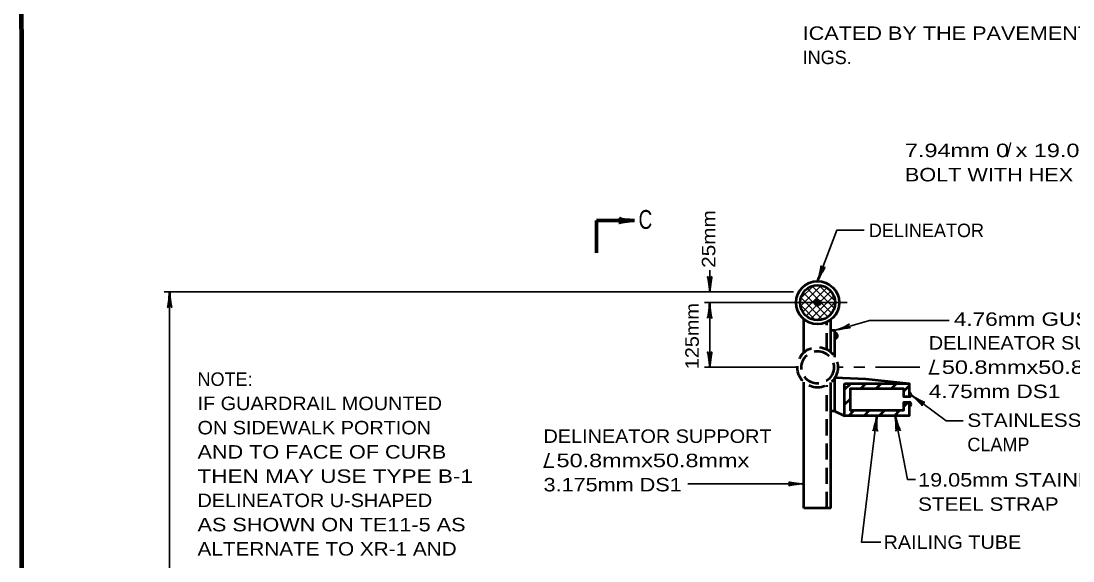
# Model space of a CAD drawing. Extents: x -105 to 751, y -65 to 479.
# Drawn here: x -47.6 to 186.6, y 91.1 to 211.4 of the extents above; entities that cross this region are included whole.
import ezdxf

# ---------------------------------------------------------------- set-up
doc = ezdxf.new("R2010")
doc.units = 0
doc.header["$LTSCALE"] = 1.2
doc.linetypes.add('MEDIUM_DASHED', pattern=[4.5, 3, -1.5])
doc.layers.add('1', color=7, linetype='Continuous', lineweight=35)

msp = doc.modelspace()

# ---------------------------------------------------------------- hatches: boundary and pattern name
at = {"layer": '1'}
msp.add_hatch(color=256, dxfattribs=at).paths.add_polyline_path([(130.319, 148.648, 1), (129.119, 148.648, 1)])

# ---------------------------------------------------------------- linework, layer by layer
at = {"layer": '1', "lineweight": 70}
for q in [(88.925, 166.96), (80.525, 159.76)]:
    msp.add_line((80.525, 166.96), q, dxfattribs=at)
at = {"layer": '1'}
for p, q in [((105.719, 151.048), (105.719, 155.848)), ((125.917, 147.83), (130.537, 152.45)), ((125.936, 149.546), (128.821, 152.431)), ((133.422, 147.424), (128.497, 152.35)), ((133.595, 148.948), (130.019, 152.525)), ((-15.697, 151.048), (124.362, 151.048)), ((-14.497, 13.539), (-14.497, 151.048)), ((126.403, 146.619), (131.748, 151.964)), ((131.98, 145.472), (126.544, 150.908)), ((127.183, 145.701), (132.666, 151.185)), ((132.838, 146.311), (127.383, 151.766)), ((128.233, 145.055), (133.312, 150.134)), ((104.519, 148.648), (136.319, 148.648)), ((105.719, 134.248), (105.719, 148.648)), ((129.274, 144.784), (125.853, 148.205)), ((130.838, 144.917), (125.989, 149.766)), ((129.629, 144.754), (133.612, 148.737)), ((132.373, 145.801), (132.549, 145.977)), ((125.219, 134.248), (104.519, 134.248)), ((135.419, 134.248), (134.219, 134.248)), ((137.819, 134.248), (140.219, 134.248)), ((142.619, 134.248), (152.441, 134.248)), ((154.502, 132.803), (156.768, 132.803)), ((68.743, 112.024), (71.008, 112.024)), ((126.693, 108.276), (100.805, 108.276))]:
    msp.add_line(p, q, dxfattribs=at)
at = {"layer": '1', "lineweight": 53}
for p, q in [((126.693, 137.579), (126.693, 144.922)), ((132.693, 137.625), (132.693, 144.881)), ((133.593, 142.481), (132.693, 142.481)), ((133.593, 136.537), (133.593, 142.481)), ((133.593, 141.881), (133.593, 140.68)), ((133.593, 124.476), (133.593, 131.959)), ((126.693, 102.876), (126.693, 130.917)), ((132.693, 102.876), (132.693, 130.871)), ((135.739, 129.323), (137.083, 130.668)), ((139.278, 129.468), (140.478, 130.668)), ((142.672, 129.468), (143.872, 130.668)), ((146.066, 129.468), (147.266, 130.668)), ((148.939, 128.947), (150.139, 130.147)), ((133.593, 126.576), (133.593, 127.776)), ((135.739, 125.929), (136.939, 127.129)), ((148.939, 125.553), (149.854, 126.468)), ((150.139, 128.567), (150.139, 127.668)), ((150.139, 126.468), (150.139, 125.568)), ((133.593, 124.476), (132.693, 124.476)), ((133.593, 124.476), (135.739, 123.468)), ((136.672, 123.468), (137.872, 124.668)), ((140.066, 123.468), (141.266, 124.668)), ((143.46, 123.468), (144.66, 124.668)), ((146.854, 123.468), (148.054, 124.668)), ((132.693, 102.876), (126.693, 102.876))]:
    msp.add_line(p, q, dxfattribs=at)
at = {"layer": '1', "linetype": 'MEDIUM_DASHED', "lineweight": 53}
for p, q in [((131.793, 138.242), (131.793, 144.319)), ((131.793, 102.876), (131.793, 130.255))]:
    msp.add_line(p, q, dxfattribs=at)
at = {"layer": '1', "lineweight": 158}
msp.add_lwpolyline([(744.128, 472.7), (-47.572, 472.6), (-47.472, -53.4)], dxfattribs=at)
at = {"layer": '1'}
for points in [[(129.719, 153.448), (134.006, 164.828), (140.107, 164.828)], [(133.593, 142.481), (141.283, 144.68), (158.977, 144.68)], [(150.531, 128.118), (158.303, 122.299), (162.127, 122.299)], [(142.939, 123.468), (139.505, 95.272), (143.774, 95.272)], [(146.995, 123.468), (149.764, 109.232), (151.513, 109.232)]]:
    msp.add_lwpolyline(points, dxfattribs=at)
at = {"layer": '1', "lineweight": 53}
msp.add_lwpolyline([(133.593, 131.959), (140.481, 131.655), (150.139, 130.668)], dxfattribs=at)
msp.add_lwpolyline([(135.739, 130.668), (150.139, 130.668), (150.139, 127.668), (148.939, 127.668), (148.939, 129.468), (136.939, 129.468), (136.939, 124.668), (148.939, 124.668), (148.939, 126.468), (150.139, 126.468), (150.139, 123.468), (135.739, 123.468)], close=True, dxfattribs=at)
for radius in [4.8, 3.9, 0.6]:
    msp.add_circle((129.719, 148.648), radius, dxfattribs=at)
at = {"layer": '1', "linetype": 'MEDIUM_DASHED', "lineweight": 53}
for radius in [4.5, 3.6]:
    msp.add_circle((129.719, 134.248), radius, dxfattribs=at)
at = {"layer": '1', "lineweight": 53}
for centre, radius, start, end in [((133.573, 141.281), 0.6, 271.87043, 88.12958), ((150.077, 128.118), 0.454, 277.89132, 82.10868), ((150.077, 126.018), 0.454, 277.89132, 82.10868)]:
    msp.add_arc(centre, radius, start, end, dxfattribs=at)
at = {"layer": '1', "lineweight": 70}
for centre, major_axis, ratio, start_param, end_param in [((87.623, 167.287), (2.145, -0.165), 0.122415, 3.1415927, 5.386832), ((87.594, 166.702), (2.105, 0.233), 0.07063, 0.8650754, 3.1424706)]:
    msp.add_ellipse(centre, major_axis=major_axis, ratio=ratio, start_param=start_param, end_param=end_param, dxfattribs=at)
at = {"layer": '1', "lineweight": 40}
for centre, major_axis, ratio, start_param, end_param in [((129.87, 154.79), (-0.58, -2.071), 0.122415, 0.8963533, 3.1415927), ((129.87, 154.79), (-0.58, -2.071), 0.122415, 0.8963533, 3.1415927), ((130.43, 154.617), (0.94, 1.898), 0.07063, 6.2823074, 8.5597026), ((130.43, 154.617), (0.94, 1.898), 0.07063, 6.2823074, 8.5597026), ((105.387, 152.358), (0.187, -2.143), 0.122415, 0.8963533, 3.1415927), ((105.387, 152.358), (0.187, -2.143), 0.122415, 0.8963533, 3.1415927), ((105.973, 152.393), (-0.211, -2.108), 0.07063, 3.1407148, 5.41811), ((105.973, 152.393), (-0.211, -2.108), 0.07063, 3.1407148, 5.41811), ((-14.751, 149.703), (0.211, 2.108), 0.07063, 3.1407148, 5.41811), ((-14.751, 149.703), (0.211, 2.108), 0.07063, 3.1407148, 5.41811), ((-14.166, 149.739), (-0.187, 2.143), 0.122415, 0.8963533, 3.1415927), ((-14.166, 149.739), (-0.187, 2.143), 0.122415, 0.8963533, 3.1415927), ((105.465, 147.303), (0.211, 2.108), 0.07063, 3.1407148, 5.41811), ((105.465, 147.303), (0.211, 2.108), 0.07063, 3.1407148, 5.41811), ((106.05, 147.339), (-0.187, 2.143), 0.122415, 0.8963533, 3.1415927), ((106.05, 147.339), (-0.187, 2.143), 0.122415, 0.8963533, 3.1415927), ((134.761, 143.159), (-2.009, -0.769), 0.122415, 0.8963533, 3.1415927), ((134.761, 143.159), (-2.009, -0.769), 0.122415, 0.8963533, 3.1415927), ((134.955, 142.606), (-2.084, -0.377), 0.07063, 3.1407148, 5.41811), ((134.955, 142.606), (-2.084, -0.377), 0.07063, 3.1407148, 5.41811), ((105.387, 135.558), (0.187, -2.143), 0.122415, 0.8963533, 3.1415927), ((105.387, 135.558), (0.187, -2.143), 0.122415, 0.8963533, 3.1415927), ((105.973, 135.593), (-0.211, -2.108), 0.07063, 3.1407148, 5.41811), ((105.973, 135.593), (-0.211, -2.108), 0.07063, 3.1407148, 5.41811), ((151.455, 127.108), (1.561, -1.432), 0.07063, 6.2823074, 8.5597026), ((151.455, 127.108), (1.561, -1.432), 0.07063, 6.2823074, 8.5597026), ((151.778, 127.598), (-1.828, 1.134), 0.122415, 0.8963533, 3.1415927), ((151.778, 127.598), (-1.828, 1.134), 0.122415, 0.8963533, 3.1415927), ((142.524, 122.163), (-0.464, -2.067), 0.07063, 6.2823074, 8.5597026), ((143.11, 122.128), (0.073, 2.15), 0.122415, 0.8963533, 3.1415927), ((147.003, 122.099), (-0.196, 2.109), 0.07063, 3.1407148, 5.41811), ((147.003, 122.099), (-0.196, 2.109), 0.07063, 3.1407148, 5.41811), ((147.571, 122.245), (-0.593, 2.068), 0.122415, 0.8963533, 3.1415927), ((147.571, 122.245), (-0.593, 2.068), 0.122415, 0.8963533, 3.1415927), ((125.383, 107.944), (2.143, 0.187), 0.122415, 0.8963533, 3.1415927), ((125.348, 108.53), (2.108, -0.211), 0.07063, 3.1407148, 5.41811)]:
    msp.add_ellipse(centre, major_axis=major_axis, ratio=ratio, start_param=start_param, end_param=end_param, dxfattribs=at)

# ---------------------------------------------------------------- texts
at = {"layer": '1'}
for s, height, width, p in [('ICATED BY THE PAVEMENT EDGE MARK-', 3, 1.2, (126.397, 207.177)), ('7.94mm 0 x 19.05mm LG. STAINLESS STEEL', 3, 1.3, (149.16, 181.065)), ('BOLT WITH HEX HD. LOCK NUT', 3, 1.2, (149.16, 175.665)), ('C', 4.2, 0.75, (89.872, 165.079)), ('4.76mm GUSSET P SEE DETAIL', 3, 1.25, (160.054, 143.482)), ('DELINEATOR SUPPORT', 3, 1.1, (154.479, 138.184)), ('/ 50.8mmx50.8mmx', 3, 1.3, (154.479, 132.784)), ('4.75mm DS1', 3, 1.25, (154.479, 127.384)), ('IF GUARDRAIL MOUNTED', 3, 1.1, (-8.291, 124.709)), ('ON SIDEWALK PORTION', 3, 1.1, (-8.291, 119.309)), ('STAINLESS STEEL', 3, 1.15, (163.056, 120.964)), ('DELINEATOR SUPPORT', 3, 1.1, (68.719, 117.405)), ('AND TO FACE OF CURB', 3, 1.2, (-8.291, 113.909)), ('/ 50.8mmx50.8mmx', 3, 1.3, (68.719, 112.005)), ('THEN MAY USE TYPE B-1', 3, 1.25, (-8.291, 108.509)), ('19.05mm STAINLESS', 3, 1.2, (152.091, 107.679)), ('3.175mm DS1', 3, 1.2, (68.719, 106.605)), ('DELINEATOR U-SHAPED', 3, 1.1, (-8.291, 103.109)), ('STEEL STRAP', 3, 1.15, (152.091, 102.279)), ('AS SHOWN ON TE11-5 AS', 3, 1.2, (-8.291, 97.709)), ('RAILING TUBE', 3, 1.1, (144.4, 93.81)), ('ALTERNATE TO XR-1 AND', 3, 1.15, (-8.291, 92.309))]:
    msp.add_text(s, height=height, dxfattribs=dict(at, width=width)).set_placement(p)
for s, p in [('INGS.', (126.397, 201.777)), ('/', (171.761, 181.168)), ('DELINEATOR', (141.126, 163.244)), ('NOTE:', (-8.291, 130.108)), ('CLAMP', (163.056, 115.564))]:
    msp.add_text(s, height=3, dxfattribs=at).set_placement(p)
for s, width, p in [('25mm', 1.15, (106.962, 156.408)), ('125mm', 1.1, (103.277, 133.83))]:
    msp.add_text(s, height=3, rotation=90, dxfattribs=dict(at, width=width)).set_placement(p)

doc.saveas('drawing.dxf')
